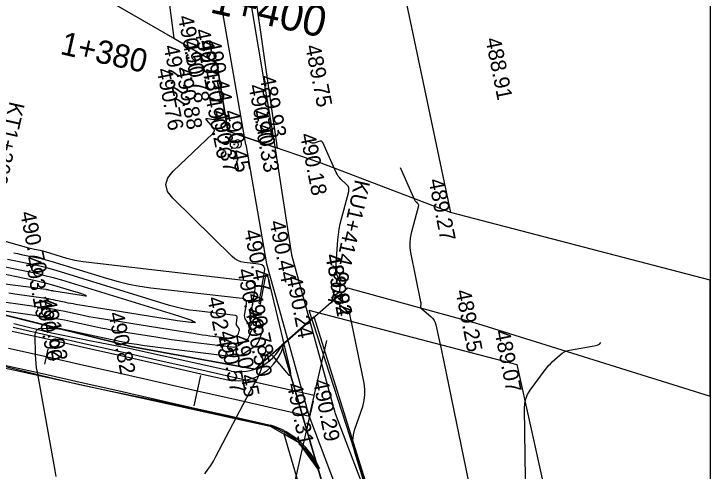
# Model space of a CAD drawing. Extents: x -636600 to -628587, y -1090963 to -1085869.
# Drawn here: x -629220.1 to -629130.1, y -1090444.3 to -1090385.3 of the extents above; entities that cross this region are included whole.
import ezdxf

# ---------------------------------------------------------------- set-up
doc = ezdxf.new("R2010")
doc.units = 0
for name, color, linetype in [('01_PARCELY_NÁVRH_PC', 7, 'Continuous'), ('08_LEGENDA_HV', 7, 'Continuous'), ('21', 7, 'Continuous'), ('30', 7, 'Continuous'), ('40', 7, 'Continuous'), ('42', 7, 'Continuous'), ('dno příkopu', 7, 'Continuous'), ('Ex_Major Contours', 7, 'Continuous'), ('Ex_Minor Contours', 7, 'Continuous'), ('HEKTOMETRY100', 7, 'Continuous'), ('HEKTOMETRY20', 7, 'Continuous'), ('HL_BODY', 7, 'Continuous'), ('koty_vše', 7, 'Continuous'), ('PARCELY_NÁVRH_SILNICE_ŽELEZNICE', 7, 'Continuous'), ('POLOMERY', 7, 'Continuous'), ('situace_osa', 7, 'Continuous'), ('situace_těleso', 7, 'Continuous'), ('situace_vozovka', 7, 'Continuous')]:
    doc.layers.add(name, color=color, linetype=linetype)

msp = doc.modelspace()

# ---------------------------------------------------------------- linework, layer by layer
at = {"layer": '01_PARCELY_NÁVRH_PC'}
for points in [[(-629211.709, -1090296.86), (-629210.298, -1090305.485), (-629199.421, -1090388.47), (-629193.855, -1090391.683), (-629192.435, -1090400.444), (-629185.987, -1090402.662), (-629190.674, -1090370.27), (-629202.536, -1090296.86)], [(-629351.806, -1090398.382), (-629222.518, -1090430.761), (-629186.936, -1090438.561), (-629183.24, -1090440.676), (-629180.737, -1090444.12), (-629185.442, -1090428.103), (-629188.944, -1090431.171), (-629204.969, -1090428.241), (-629236.985, -1090420.294), (-629268.755, -1090411.534), (-629342.71, -1090393.203)], [(-629160.039, -1090488.385), (-629160.822, -1090487.672), (-629168.119, -1090470.358), (-629170.784, -1090457.931), (-629181.254, -1090424.434), (-629185.442, -1090428.103), (-629167.879, -1090487.898), (-629167.511, -1090488.385)], [(-629167.511, -1090488.385), (-629167.879, -1090487.898), (-629180.737, -1090444.12), (-629183.24, -1090440.676), (-629185.206, -1090439.551), (-629170.863, -1090488.385)]]:
    msp.add_lwpolyline(points, dxfattribs=at)
at = {"layer": '08_LEGENDA_HV'}
msp.add_line((-629130.105, -1090296.86), (-629130.105, -1090593.86), dxfattribs=at)
at = {"layer": '21'}
for p, q in [((-629193.855, -1090391.683), (-629214.576, -1090379.723)), ((-629192.435, -1090400.444), (-629193.855, -1090391.683)), ((-629180.345, -1090404.602), (-629192.435, -1090400.444)), ((-629163.633, -1090410.944), (-629180.345, -1090404.602)), ((-629130.105, -1090419.706), (-629163.633, -1090410.944)), ((-629236.985, -1090420.294), (-629213.841, -1090425.963)), ((-629188.944, -1090431.171), (-629176.974, -1090420.684)), ((-629176.974, -1090420.684), (-629160.151, -1090425.271)), ((-629213.841, -1090425.963), (-629204.969, -1090428.241)), ((-629160.151, -1090425.271), (-629130.105, -1090434.667)), ((-629204.969, -1090428.241), (-629188.944, -1090431.171))]:
    msp.add_line(p, q, dxfattribs=at)
at = {"layer": '30'}
for radius in [0.5, 0.0327]:
    msp.add_circle((-629191.6, -1090402.188), radius, dxfattribs=at)
msp.add_arc((-629191.146, -1090402.098), 0.5, 253.00048, 129.99572, dxfattribs=at)
at = {"layer": '40'}
for p, q in [((-629190.086, -1090402.16), (-629199.633, -1090347.564)), ((-629195.675, -1090347.218), (-629186.395, -1090402.162)), ((-629190.086, -1090402.16), (-629187.445, -1090417.591)), ((-629186.395, -1090402.162), (-629184.182, -1090416.414)), ((-629184.182, -1090416.414), (-629178.557, -1090436.922)), ((-629187.445, -1090417.591), (-629181.964, -1090437.169)), ((-629181.976, -1090423.582), (-629170.784, -1090457.931)), ((-629178.557, -1090436.922), (-629173.893, -1090449.138)), ((-629181.964, -1090437.169), (-629176.525, -1090451.444))]:
    msp.add_line(p, q, dxfattribs=at)
at = {"layer": '42'}
for p, q in [((-629173.56, -1090363.998), (-629163.633, -1090410.944)), ((-629181.976, -1090423.582), (-629155.095, -1090430.569)), ((-629155.095, -1090430.569), (-629144.629, -1090477.56))]:
    msp.add_line(p, q, dxfattribs=at)
at = {"layer": 'dno příkopu'}
msp.add_lwpolyline([(-629220.172, -1090425.781), (-629215.295, -1090426.882), (-629210.418, -1090427.983), (-629205.541, -1090429.083), (-629200.663, -1090430.184), (-629195.786, -1090431.285), (-629190.909, -1090432.386), (-629186.031, -1090433.486), (-629181.248, -1090434.566)], dxfattribs=at)
at = {"layer": 'Ex_Major Contours'}
for points in [[(-629172.99, -1090451.654), (-629176.032, -1090441.89), (-629176.203, -1090441.149), (-629176.254, -1090440.409), (-629176.185, -1090439.671), (-629175.996, -1090438.934), (-629174.999, -1090435.99), (-629174.801, -1090435.25), (-629174.704, -1090434.505), (-629174.709, -1090433.753), (-629174.815, -1090432.995), (-629176.409, -1090425.271), (-629176.436, -1090425.143), (-629176.463, -1090425.015), (-629176.49, -1090424.887), (-629176.518, -1090424.759), (-629176.63, -1090424.247), (-629176.666, -1090424.125), (-629176.721, -1090424.013), (-629176.794, -1090423.912), (-629176.885, -1090423.822), (-629178.861, -1090422.144), (-629178.956, -1090422.038), (-629178.982, -1090421.937), (-629178.94, -1090421.841), (-629178.83, -1090421.752), (-629178.201, -1090421.372), (-629178.096, -1090421.292), (-629178.016, -1090421.196), (-629177.961, -1090421.084), (-629177.931, -1090420.955), (-629177.863, -1090420.407), (-629177.855, -1090420.272), (-629177.865, -1090420.139), (-629177.894, -1090420.009), (-629177.94, -1090419.881), (-629178.34, -1090418.978), (-629178.412, -1090418.783), (-629178.46, -1090418.584), (-629178.482, -1090418.38), (-629178.479, -1090418.173), (-629178.202, -1090414.477), (-629178.135, -1090413.794), (-629178.036, -1090413.116), (-629177.905, -1090412.444), (-629177.743, -1090411.777), (-629176.803, -1090408.264), (-629176.767, -1090408.015), (-629176.796, -1090407.785), (-629176.892, -1090407.573), (-629177.053, -1090407.381), (-629177.829, -1090406.646), (-629178.012, -1090406.455), (-629178.174, -1090406.249), (-629178.315, -1090406.027), (-629178.434, -1090405.791), (-629180.152, -1090401.94), (-629180.223, -1090401.827), (-629180.314, -1090401.761), (-629180.425, -1090401.742), (-629180.555, -1090401.77), (-629181.118, -1090401.978), (-629181.258, -1090402.015), (-629181.396, -1090402.024), (-629181.534, -1090402.004), (-629181.67, -1090401.955), (-629181.915, -1090401.841)], [(-629223.772, -1090417.439), (-629218.233, -1090418.576), (-629217.146, -1090418.812), (-629216.066, -1090419.074), (-629214.993, -1090419.361), (-629213.926, -1090419.674), (-629198.786, -1090424.31), (-629197.125, -1090424.861), (-629196.595, -1090425.148), (-629197.197, -1090425.173), (-629198.931, -1090424.935), (-629212.086, -1090422.821), (-629212.408, -1090422.767), (-629212.728, -1090422.709), (-629213.048, -1090422.646), (-629213.367, -1090422.579), (-629214.641, -1090422.303), (-629214.96, -1090422.237), (-629215.281, -1090422.176), (-629215.602, -1090422.122), (-629215.924, -1090422.073), (-629219.955, -1090421.503), (-629220.735, -1090421.394)]]:
    msp.add_lwpolyline(points, dxfattribs=at)
at = {"layer": 'Ex_Minor Contours'}
for points in [[(-629195.409, -1090444.683), (-629195.009, -1090444.154), (-629194.636, -1090443.609), (-629194.289, -1090443.046), (-629193.968, -1090442.466), (-629189.546, -1090434.01), (-629189.453, -1090433.836), (-629189.355, -1090433.664), (-629189.254, -1090433.494), (-629189.149, -1090433.326), (-629188.723, -1090432.66), (-629188.621, -1090432.491), (-629188.53, -1090432.317), (-629188.449, -1090432.138), (-629188.379, -1090431.954), (-629187.562, -1090429.623), (-629187.386, -1090429.274), (-629187.173, -1090429.131), (-629186.923, -1090429.191), (-629186.637, -1090429.457), (-629184.853, -1090431.607), (-629184.522, -1090431.952), (-629184.327, -1090432.025), (-629184.267, -1090431.825), (-629184.343, -1090431.353), (-629187.153, -1090419.492), (-629187.28, -1090419.081), (-629187.401, -1090418.946), (-629187.516, -1090419.086), (-629187.625, -1090419.503), (-629188.25, -1090422.779), (-629188.256, -1090422.798), (-629188.264, -1090422.805), (-629188.274, -1090422.802), (-629188.287, -1090422.787), (-629188.341, -1090422.706), (-629188.353, -1090422.685), (-629188.36, -1090422.663), (-629188.363, -1090422.641), (-629188.361, -1090422.617), (-629187.676, -1090418.636), (-629187.664, -1090418.23), (-629187.788, -1090417.924), (-629188.046, -1090417.719), (-629188.44, -1090417.616), (-629190.282, -1090417.403), (-629190.726, -1090417.316), (-629191.138, -1090417.161), (-629191.517, -1090416.938), (-629191.864, -1090416.647), (-629199.527, -1090409.12), (-629200.201, -1090408.236), (-629200.42, -1090407.356), (-629200.184, -1090406.481), (-629199.492, -1090405.61), (-629194.368, -1090400.771), (-629194.218, -1090400.583), (-629194.161, -1090400.389), (-629194.196, -1090400.191), (-629194.325, -1090399.988), (-629195.127, -1090399.041), (-629195.211, -1090398.918), (-629195.218, -1090398.84), (-629195.147, -1090398.806), (-629194.999, -1090398.817), (-629194.252, -1090398.948), (-629194.092, -1090398.953), (-629193.983, -1090398.902), (-629193.926, -1090398.797), (-629193.922, -1090398.636), (-629193.941, -1090398.472)], [(-629170.165, -1090405.132), (-629168.297, -1090409.321), (-629168.259, -1090409.395), (-629168.215, -1090409.465), (-629168.164, -1090409.53), (-629168.106, -1090409.59), (-629167.861, -1090409.821), (-629167.811, -1090409.882), (-629167.781, -1090409.949), (-629167.771, -1090410.021), (-629167.783, -1090410.1), (-629168.732, -1090413.648), (-629168.861, -1090414.267), (-629168.916, -1090414.889), (-629168.898, -1090415.513), (-629168.806, -1090416.139), (-629167.505, -1090422.481), (-629167.492, -1090422.558), (-629167.485, -1090422.635), (-629167.483, -1090422.713), (-629167.488, -1090422.791), (-629167.516, -1090423.103), (-629167.514, -1090423.177), (-629167.496, -1090423.245), (-629167.462, -1090423.306), (-629167.41, -1090423.36), (-629166.13, -1090424.448), (-629165.917, -1090424.659), (-629165.747, -1090424.895), (-629165.619, -1090425.156), (-629165.532, -1090425.442), (-629165.146, -1090427.212), (-629165.061, -1090427.606), (-629164.977, -1090428.001), (-629164.893, -1090428.396), (-629164.811, -1090428.792), (-629160.669, -1090448.865)], [(-629214.608, -1090445.031), (-629214.717, -1090444.261), (-629217.039, -1090431.595), (-629217.13, -1090431.03), (-629217.198, -1090430.462), (-629217.242, -1090429.893), (-629217.263, -1090429.321), (-629217.301, -1090426.747), (-629217.253, -1090426.37), (-629217.095, -1090426.103), (-629216.827, -1090425.947), (-629216.449, -1090425.902), (-629214.717, -1090425.944), (-629214.285, -1090425.964), (-629213.856, -1090426.005), (-629213.429, -1090426.067), (-629213.005, -1090426.148), (-629206.225, -1090427.619), (-629205.973, -1090427.672), (-629205.721, -1090427.721), (-629205.469, -1090427.767), (-629205.215, -1090427.81), (-629204.201, -1090427.973), (-629203.947, -1090428.012), (-629203.693, -1090428.05), (-629203.439, -1090428.085), (-629203.184, -1090428.118), (-629191.835, -1090429.534), (-629191.47, -1090429.549), (-629191.119, -1090429.502), (-629190.783, -1090429.392), (-629190.461, -1090429.22), (-629189.043, -1090428.307), (-629188.824, -1090428.14), (-629188.64, -1090427.946), (-629188.491, -1090427.723), (-629188.377, -1090427.473), (-629187.992, -1090426.415), (-629187.927, -1090426.154), (-629187.926, -1090425.901), (-629187.989, -1090425.656), (-629188.115, -1090425.419), (-629188.973, -1090424.154), (-629189.137, -1090423.858), (-629189.237, -1090423.549), (-629189.274, -1090423.226), (-629189.247, -1090422.889), (-629188.892, -1090420.828), (-629188.881, -1090420.42), (-629189.005, -1090420.114), (-629189.264, -1090419.909), (-629189.658, -1090419.805), (-629211.137, -1090417.327), (-629211.67, -1090417.254), (-629212.197, -1090417.156), (-629212.719, -1090417.035), (-629213.236, -1090416.889), (-629215.97, -1090416.052), (-629216.147, -1090416), (-629216.326, -1090415.952), (-629216.505, -1090415.909), (-629216.686, -1090415.869), (-629217.41, -1090415.721), (-629217.591, -1090415.682), (-629217.77, -1090415.64), (-629217.95, -1090415.594), (-629218.128, -1090415.546), (-629227.687, -1090412.838)], [(-629220.1, -1090416.158), (-629219.62, -1090416.271), (-629219.137, -1090416.374), (-629217.201, -1090416.771), (-629216.719, -1090416.876), (-629216.239, -1090416.993), (-629215.762, -1090417.12), (-629215.289, -1090417.259), (-629207.983, -1090419.496), (-629206.601, -1090419.885), (-629205.206, -1090420.21), (-629203.797, -1090420.471), (-629202.375, -1090420.668), (-629190.552, -1090422.032), (-629190.295, -1090422.1), (-629190.126, -1090422.233), (-629190.046, -1090422.432), (-629190.053, -1090422.698), (-629190.284, -1090424.04), (-629190.302, -1090424.259), (-629190.278, -1090424.469), (-629190.213, -1090424.671), (-629190.106, -1090424.863), (-629189.547, -1090425.687), (-629189.465, -1090425.842), (-629189.424, -1090426.001), (-629189.425, -1090426.166), (-629189.467, -1090426.335), (-629189.718, -1090427.024), (-629189.792, -1090427.187), (-629189.889, -1090427.332), (-629190.009, -1090427.459), (-629190.151, -1090427.567), (-629191.074, -1090428.162), (-629191.284, -1090428.274), (-629191.503, -1090428.345), (-629191.731, -1090428.376), (-629191.969, -1090428.366), (-629197.639, -1090427.659), (-629198.664, -1090427.526), (-629199.688, -1090427.385), (-629200.71, -1090427.234), (-629201.731, -1090427.075), (-629206.475, -1090426.312), (-629207.266, -1090426.18), (-629208.054, -1090426.037), (-629208.841, -1090425.883), (-629209.626, -1090425.718), (-629212.76, -1090425.038), (-629213.545, -1090424.875), (-629214.332, -1090424.727), (-629215.122, -1090424.593), (-629215.915, -1090424.473), (-629229.556, -1090422.545)], [(-629224.53, -1090422.056), (-629215.919, -1090423.273), (-629215.362, -1090423.357), (-629214.806, -1090423.452), (-629214.253, -1090423.556), (-629213.701, -1090423.67), (-629211.496, -1090424.149), (-629210.945, -1090424.264), (-629210.391, -1090424.373), (-629209.837, -1090424.473), (-629209.281, -1090424.567), (-629196.634, -1090426.599), (-629196.16, -1090426.673), (-629195.685, -1090426.743), (-629195.21, -1090426.808), (-629194.734, -1090426.87), (-629192.103, -1090427.198), (-629191.993, -1090427.203), (-629191.887, -1090427.189), (-629191.785, -1090427.155), (-629191.688, -1090427.104), (-629191.26, -1090426.828), (-629191.193, -1090426.777), (-629191.138, -1090426.718), (-629191.093, -1090426.651), (-629191.058, -1090426.575), (-629190.942, -1090426.256), (-629190.922, -1090426.177), (-629190.922, -1090426.101), (-629190.941, -1090426.027), (-629190.979, -1090425.955), (-629191.238, -1090425.573), (-629191.288, -1090425.483), (-629191.318, -1090425.39), (-629191.329, -1090425.292), (-629191.321, -1090425.19), (-629191.214, -1090424.568), (-629191.21, -1090424.445), (-629191.248, -1090424.352), (-629191.326, -1090424.29), (-629191.445, -1090424.259), (-629196.486, -1090423.677), (-629197.368, -1090423.555), (-629198.242, -1090423.393), (-629199.108, -1090423.192), (-629199.965, -1090422.95), (-629214.608, -1090418.467), (-629215.378, -1090418.241), (-629216.153, -1090418.033), (-629216.933, -1090417.844), (-629217.717, -1090417.674), (-629220.898, -1090417.021)], [(-629226.334, -1090419.525), (-629217.86, -1090420.606), (-629217.649, -1090420.633), (-629217.438, -1090420.661), (-629217.228, -1090420.69), (-629217.017, -1090420.719), (-629215.928, -1090420.873), (-629215.841, -1090420.886), (-629215.755, -1090420.901), (-629215.668, -1090420.917), (-629215.582, -1090420.935), (-629215.238, -1090421.01), (-629215.152, -1090421.028), (-629215.065, -1090421.045), (-629214.979, -1090421.061), (-629214.892, -1090421.075), (-629211.339, -1090421.646), (-629210.871, -1090421.71), (-629210.708, -1090421.704), (-629210.851, -1090421.626), (-629211.3, -1090421.477), (-629214.497, -1090420.498), (-629215.232, -1090420.283), (-629215.972, -1090420.085), (-629216.717, -1090419.904), (-629217.466, -1090419.741), (-629226.646, -1090417.858)], [(-629153.743, -1090460.416), (-629154.099, -1090436.27), (-629154.058, -1090435.628), (-629153.919, -1090435.018), (-629153.679, -1090434.44), (-629153.34, -1090433.894), (-629151.413, -1090431.268), (-629151.203, -1090430.995), (-629150.979, -1090430.735), (-629150.743, -1090430.486), (-629150.494, -1090430.249), (-629149.47, -1090429.325), (-629149.204, -1090429.115), (-629148.916, -1090428.949), (-629148.608, -1090428.825), (-629148.279, -1090428.744), (-629145.077, -1090428.185), (-629144.698, -1090428.08), (-629144.368, -1090427.903), (-629144.213, -1090427.766)]]:
    msp.add_lwpolyline(points, dxfattribs=at)
at = {"layer": 'HEKTOMETRY100'}
for points in [[(-629195.951, -1090432.017), (-629196.832, -1090435.918)], [(-629181.413, -1090435.298), (-629182.294, -1090439.2)]]:
    msp.add_lwpolyline(points, dxfattribs=at)
at = {"layer": 'HEKTOMETRY20'}
for points in [[(-629215.68, -1090428.589), (-629216.121, -1090430.54)], [(-629181.633, -1090436.273), (-629182.073, -1090438.224)]]:
    msp.add_lwpolyline(points, dxfattribs=at)
at = {"layer": 'HL_BODY'}
msp.add_lwpolyline([(-629181.853, -1090437.249), (-629179.652, -1090427.494)], dxfattribs=at)
at = {"layer": 'PARCELY_NÁVRH_SILNICE_ŽELEZNICE'}
msp.add_line((-629130.105, -1090434.667), (-629130.105, -1090419.706), dxfattribs=at)
for points in [[(-629605.575, -1090296.86), (-629591.052, -1090304.21), (-629561.855, -1090321.748), (-629545.359, -1090334.769), (-629498.696, -1090345.634), (-629454.812, -1090359.914), (-629438.615, -1090363.656), (-629342.71, -1090393.203), (-629268.755, -1090411.534), (-629236.985, -1090420.294), (-629204.969, -1090428.241), (-629188.944, -1090431.171), (-629176.974, -1090420.684), (-629160.151, -1090425.271), (-629130.105, -1090434.667)], [(-629130.105, -1090419.706), (-629163.633, -1090410.944), (-629180.345, -1090404.602), (-629192.435, -1090400.444), (-629193.855, -1090391.683), (-629214.576, -1090379.723), (-629277.106, -1090359.525), (-629343.27, -1090339.049), (-629375.976, -1090328.394), (-629483.018, -1090296.86)]]:
    msp.add_lwpolyline(points, dxfattribs=at)
at = {"layer": 'POLOMERY'}
msp.add_lwpolyline([(-629181.853, -1090437.249), (-629184.055, -1090447.003)], dxfattribs=at)
at = {"layer": 'situace_osa'}
msp.add_lwpolyline([(-629220.778, -1090428.464), (-629215.901, -1090429.564), (-629211.023, -1090430.665), (-629206.146, -1090431.766), (-629201.269, -1090432.867), (-629196.391, -1090433.967), (-629191.514, -1090435.068), (-629186.637, -1090436.169), (-629181.853, -1090437.249)], dxfattribs=at)
at = {"layer": 'situace_těleso'}
for points in [[(-629192.015, -1090431.446), (-629195.64, -1090430.639), (-629200.522, -1090429.559), (-629205.407, -1090428.493), (-629210.318, -1090427.539), (-629215.217, -1090426.537), (-629220.069, -1090425.324)], [(-629221.31, -1090430.819), (-629216.452, -1090432.008), (-629211.586, -1090433.157), (-629206.695, -1090434.197), (-629201.794, -1090435.195), (-629196.912, -1090436.275), (-629192.036, -1090437.382), (-629187.165, -1090438.508), (-629186.936, -1090438.561)]]:
    msp.add_lwpolyline(points, dxfattribs=at)
for centre, radius, start, end in [((-629191.019, -1090425.27), 6.256, 260.84277, 333.07028), ((-629190.017, -1090448.232), 10.15, 23.89645, 72.32683)]:
    msp.add_arc(centre, radius, start, end, dxfattribs=at)
at = {"layer": 'situace_vozovka'}
for points in [[(-629220.283, -1090426.269), (-629215.405, -1090427.37), (-629210.528, -1090428.47), (-629205.651, -1090429.571), (-629200.773, -1090430.672), (-629195.896, -1090431.773), (-629192.256, -1090432.594)], [(-629221.273, -1090430.658), (-629216.396, -1090431.759), (-629211.519, -1090432.86), (-629206.641, -1090433.961), (-629201.764, -1090435.061), (-629196.887, -1090436.162), (-629192.009, -1090437.263), (-629187.132, -1090438.364), (-629186.902, -1090438.416)]]:
    msp.add_lwpolyline(points, dxfattribs=at)
for centre, radius, start, end in [((-629191.215, -1090426.461), 6.221, 260.37175, 345.71857), ((-629189.857, -1090448.132), 10.156, 23.67569, 73.08435)]:
    msp.add_arc(centre, radius, start, end, dxfattribs=at)

# ---------------------------------------------------------------- texts
at = {"layer": 'HEKTOMETRY100'}
msp.add_text('1+400', height=4, rotation=347.28176, dxfattribs=at).set_placement((-629194.871, -1090385.103))
at = {"layer": 'HEKTOMETRY20'}
msp.add_text('1+380', height=3, rotation=347.28176, dxfattribs=at).set_placement((-629214.21, -1090390.477))
at = {"layer": 'HL_BODY'}
for s, p in [('KT1+369,137', (-629220.608, -1090396.538)), ('KU1+414,904', (-629175.964, -1090406.614))]:
    msp.add_text(s, height=2, rotation=257.28176, dxfattribs=at).set_placement(p)
at = {"layer": 'koty_vše'}
for s, p in [('490.50', (-629198.898, -1090385.682)), ('490.45', (-629196.738, -1090387.422)), ('490.78', (-629198.255, -1090388.926)), ('490.30', (-629196.303, -1090388.848)), ('490.44', (-629195.362, -1090388.862)), ('488.91', (-629159.14, -1090388.556)), ('492.22', (-629200.74, -1090389.506)), ('489.75', (-629182.436, -1090389.477)), ('490.76', (-629201.635, -1090392.496)), ('490.88', (-629199.204, -1090392.366)), ('489.93', (-629188.336, -1090393.401)), ('490.40', (-629189.782, -1090394.59)), ('490.26', (-629195.329, -1090396.129)), ('490.37', (-629194.484, -1090397.924)), ('490.45', (-629192.969, -1090397.899)), ('490.33', (-629189.279, -1090397.902)), ('490.18', (-629183.118, -1090400.898)), ('489.27', (-629166.5, -1090406.769)), ('490.70', (-629219.277, -1090410.987)), ('490.44', (-629187.065, -1090412.153)), ('490.47', (-629190.329, -1090413.33)), ('493.19', (-629218.684, -1090416.805)), ('489.82', (-629179.841, -1090416.508)), ('489.94', (-629179.83, -1090416.458)), ('490.48', (-629191.216, -1090418.369)), ('490.24', (-629184.86, -1090419.321)), ('490.78', (-629190, -1090421.574)), ('489.25', (-629163.018, -1090421.095)), ('490.90', (-629217.284, -1090422.277)), ('491.02', (-629216.615, -1090422.258)), ('492.43', (-629195.083, -1090422.007)), ('490.82', (-629207.853, -1090423.981)), ('490.50', (-629190.206, -1090424.289)), ('490.57', (-629193.628, -1090426.412)), ('490.45', (-629191.827, -1090426.911)), ('489.07', (-629157.978, -1090426.308)), ('490.31', (-629184.802, -1090433.14)), ('490.29', (-629181.442, -1090432.653))]:
    msp.add_text(s, height=2, rotation=281.21136, dxfattribs=at).set_placement(p)

doc.saveas('drawing.dxf')
